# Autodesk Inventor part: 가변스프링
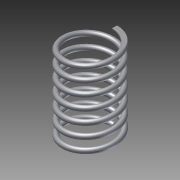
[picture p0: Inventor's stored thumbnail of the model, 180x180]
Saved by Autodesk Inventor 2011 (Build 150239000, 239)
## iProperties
Created: 2014-12
Part Number: 가변스프링
Document SubType Name: Modeling
Designer: user
Density: 1 g/cm^3
Author: user
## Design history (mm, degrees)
sketch "스케치2"
  geometry: L1 (0, 0)-(24, 0); L2 (24, 0)-(24, 84.25); L3 (24, 84.25)-(0, 84.25); L4 (0, 84.25)-(0, 0); C1 r 2.5 at (24, 0)
  constraints: 8 end point, 2 parallel, 1 centre point, 1 coincident, 1 horizontal, 1 perpendicular
  dimensions: "d0" = 5 diameter of C1; "d1" = 48 diameter of L2 L4; "d2" = 84.25 distance between parallel lines of L1 L3 (derived)
feature "코일1" pitch "d3" = 10; turns "d5" = 7; dims "d4" = 84.25 (= d2), "d6" = 0, angle "d7" = 90 deg, angle "d8" = 90 deg, "d9" = 0, "d10" = 0
node "작업 평면1"
feature "분할1"
feature "분할2"
node "솔리드1"
other parameters: "d11" = 84.25
